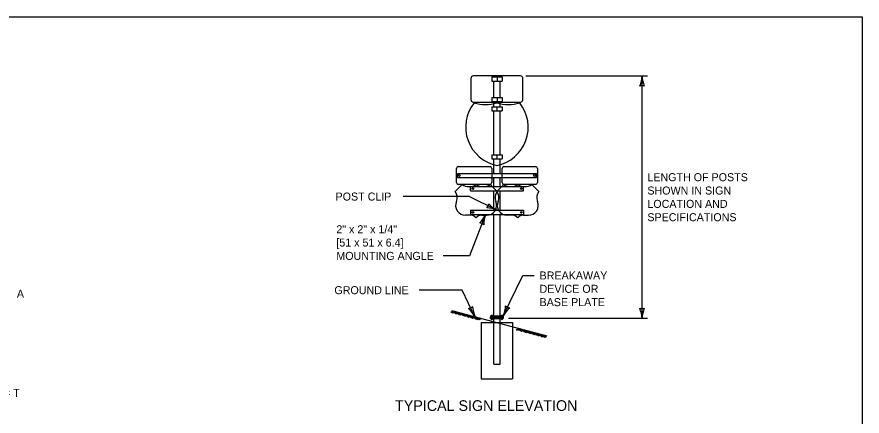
# Model space of a CAD drawing. Extents: x 49991 to 81321, y 49988 to 50028.
# Drawn here: x 50010.41 to 50016.75, y 49996.01 to 49999 of the extents above; entities that cross this region are included whole.
import ezdxf

# ---------------------------------------------------------------- set-up
doc = ezdxf.new("R2010")
doc.units = 0
for name, color, linetype in [('Level 1', 7, 'Continuous'), ('Level 2', 7, 'Continuous'), ('Level 3', 7, 'Continuous'), ('Level 4', 7, 'Continuous')]:
    doc.layers.add(name, color=color, linetype=linetype)

msp = doc.modelspace()

# ---------------------------------------------------------------- linework, layer by layer
at = {"layer": 'Level 1'}
for p, q in [((50013.9732, 49998.5488), (50014.0513, 49998.5488)), ((50013.9732, 49998.5488), (50013.9732, 49998.5175)), ((50014.0122, 49998.5488), (50014.0122, 49998.5175)), ((50014.0513, 49998.5488), (50014.0513, 49998.5175)), ((50013.9732, 49998.5175), (50014.0513, 49998.5175)), ((50013.9888, 49998.3957), (50013.9888, 49998.5175)), ((50014.0357, 49998.3957), (50014.0357, 49998.5175)), ((50013.9732, 49998.3957), (50014.0513, 49998.3957)), ((50013.9732, 49998.3957), (50013.9732, 49998.3644)), ((50013.9732, 49998.3644), (50014.0513, 49998.3644)), ((50013.9881, 49998.3254), (50013.9881, 49998.3644)), ((50014.0122, 49998.3957), (50014.0122, 49998.3644)), ((50014.035, 49998.3254), (50014.035, 49998.3644)), ((50014.0513, 49998.3957), (50014.0513, 49998.3644)), ((50013.9725, 49998.3254), (50014.0506, 49998.3254)), ((50013.9725, 49998.3254), (50013.9725, 49998.2942)), ((50013.9725, 49998.2942), (50014.0506, 49998.2942)), ((50013.9881, 49997.9661), (50013.9881, 49998.2942)), ((50014.0116, 49998.3254), (50014.0116, 49998.2942)), ((50014.035, 49997.9661), (50014.035, 49998.2942)), ((50014.0506, 49998.3254), (50014.0506, 49998.2942)), ((50013.9725, 49997.9661), (50014.0506, 49997.9661)), ((50013.9725, 49997.9661), (50013.9725, 49997.9348)), ((50013.9725, 49997.9348), (50014.0506, 49997.9348)), ((50013.9881, 49997.8254), (50013.9881, 49997.9348)), ((50014.0116, 49997.9661), (50014.0116, 49997.9348)), ((50014.035, 49997.8254), (50014.035, 49997.9348)), ((50014.0506, 49997.9661), (50014.0506, 49997.9348)), ((50013.7149, 49997.8254), (50014.3082, 49997.8254)), ((50013.7149, 49997.7942), (50013.7149, 49997.8254)), ((50013.7149, 49997.7942), (50014.3082, 49997.7942)), ((50013.9881, 49997.7273), (50013.9881, 49997.7942)), ((50014.035, 49997.7273), (50014.035, 49997.7942)), ((50014.3082, 49997.7942), (50014.3082, 49997.8254)), ((50013.814, 49997.7273), (50014.2105, 49997.7273)), ((50013.814, 49997.6961), (50013.814, 49997.7273)), ((50014.2105, 49997.6961), (50014.2105, 49997.7273)), ((50013.814, 49997.6961), (50014.2105, 49997.6961)), ((50013.9881, 49997.5497), (50013.9881, 49997.6961)), ((50014.035, 49997.5497), (50014.035, 49997.6961)), ((50013.814, 49997.5497), (50014.2105, 49997.5497)), ((50013.814, 49997.5497), (50013.814, 49997.5184)), ((50014.2105, 49997.5497), (50014.2105, 49997.5184)), ((50013.814, 49997.5184), (50014.2105, 49997.5184)), ((50013.9881, 49996.3944), (50013.9881, 49997.5184)), ((50014.035, 49996.3944), (50014.035, 49997.5184)), ((50013.666, 49996.7843), (50013.6852, 49996.7954)), ((50013.6712, 49996.7829), (50013.6904, 49996.7939)), ((50013.6718, 49996.7987), (50014.3847, 49996.6075)), ((50013.6766, 49996.7814), (50013.6956, 49996.7925)), ((50013.6862, 49996.7872), (50013.6917, 49996.7774)), ((50013.691, 49996.7899), (50013.6981, 49996.7774)), ((50013.6956, 49996.7925), (50013.7028, 49996.7801)), ((50013.6966, 49996.7759), (50013.7157, 49996.7869)), ((50013.7018, 49996.7744), (50013.721, 49996.7855)), ((50013.7072, 49996.7731), (50013.7262, 49996.7842)), ((50013.7168, 49996.7787), (50013.7224, 49996.7689)), ((50013.7216, 49996.7814), (50013.7287, 49996.7689)), ((50013.7262, 49996.7842), (50013.7335, 49996.7717)), ((50013.7281, 49996.7673), (50013.7474, 49996.7784)), ((50013.7335, 49996.7659), (50013.7525, 49996.7769)), ((50013.7387, 49996.7644), (50013.7578, 49996.7755)), ((50013.7531, 49996.7729), (50013.7604, 49996.7604)), ((50013.7578, 49996.7755), (50013.765, 49996.7631)), ((50013.7485, 49996.7701), (50013.754, 49996.7604)), ((50013.7595, 49996.7594), (50013.7787, 49996.7705)), ((50013.7648, 49996.7581), (50013.784, 49996.7692)), ((50013.7702, 49996.7567), (50013.7892, 49996.7677)), ((50013.7798, 49996.7623), (50013.7854, 49996.7525)), ((50013.7845, 49996.7651), (50013.7917, 49996.7525)), ((50013.7892, 49996.7677), (50013.7965, 49996.7552)), ((50013.7904, 49996.7504), (50013.8095, 49996.7614)), ((50013.7956, 49996.7489), (50013.8147, 49996.7601)), ((50013.801, 49996.7475), (50013.82, 49996.7587)), ((50013.8106, 49996.7532), (50013.8161, 49996.7435)), ((50013.8154, 49996.7561), (50013.8225, 49996.7435)), ((50013.82, 49996.7587), (50013.8272, 49996.7462)), ((50013.8215, 49996.7423), (50013.8406, 49996.7534)), ((50013.8267, 49996.7409), (50013.8457, 49996.7519)), ((50013.832, 49996.7394), (50013.8511, 49996.7505)), ((50013.8417, 49996.7451), (50013.8472, 49996.7354)), ((50013.8465, 49996.7479), (50013.8536, 49996.7354)), ((50013.8511, 49996.7505), (50013.8582, 49996.7381)), ((50013.8518, 49996.7338), (50013.8711, 49996.7449)), ((50013.8572, 49996.7324), (50013.8762, 49996.7435)), ((50013.8625, 49996.7311), (50013.8816, 49996.7422)), ((50013.8722, 49996.7367), (50013.8777, 49996.7269)), ((50013.8768, 49996.7394), (50013.8841, 49996.7269)), ((50013.8816, 49996.7422), (50013.8887, 49996.7297)), ((50013.9645, 49996.7572), (50014.0586, 49996.7572)), ((50013.9645, 49996.7572), (50013.9645, 49996.7487)), ((50013.9645, 49996.7487), (50014.0586, 49996.7487)), ((50013.9645, 49996.7472), (50014.0586, 49996.7472)), ((50013.9645, 49996.7387), (50013.9645, 49996.7472)), ((50013.9645, 49996.7387), (50014.0586, 49996.7387)), ((50013.9786, 49996.7577), (50013.9686, 49996.7577)), ((50013.9686, 49996.7577), (50013.9686, 49996.7572)), ((50013.9783, 49996.7572), (50013.9686, 49996.7572)), ((50013.9686, 49996.7487), (50013.9686, 49996.7472)), ((50013.9686, 49996.7381), (50013.9686, 49996.7387)), ((50013.9686, 49996.7381), (50013.9783, 49996.7381)), ((50013.9693, 49996.7577), (50013.9693, 49996.7609)), ((50013.9693, 49996.7381), (50013.9693, 49996.7349)), ((50013.9703, 49996.7619), (50013.9768, 49996.7619)), ((50013.9703, 49996.7339), (50013.9768, 49996.7339)), ((50013.9703, 49996.7339), (50013.9768, 49996.7339)), ((50013.9708, 49996.7577), (50013.9708, 49996.7572)), ((50013.9708, 49996.7381), (50013.9708, 49996.7387)), ((50013.9714, 49996.7577), (50013.9714, 49996.7609)), ((50013.9714, 49996.7572), (50013.9714, 49996.7387)), ((50013.9714, 49996.7381), (50013.9714, 49996.7349)), ((50013.9717, 49996.7335), (50013.9758, 49996.7339)), ((50013.9717, 49996.7329), (50013.9758, 49996.7332)), ((50013.9717, 49996.7323), (50013.9758, 49996.7326)), ((50013.9717, 49996.7316), (50013.9758, 49996.732)), ((50013.9717, 49996.731), (50013.9758, 49996.7313)), ((50013.9717, 49996.7304), (50013.9758, 49996.7307)), ((50013.9717, 49996.7297), (50013.9758, 49996.7301)), ((50013.9717, 49996.7297), (50013.9755, 49996.7297)), ((50013.9736, 49996.7387), (50013.9736, 49996.7281)), ((50013.9758, 49996.7577), (50013.9758, 49996.7609)), ((50013.9758, 49996.7572), (50013.9758, 49996.7387)), ((50013.9758, 49996.7381), (50013.9758, 49996.7349)), ((50013.9764, 49996.7577), (50013.9764, 49996.7572)), ((50013.9764, 49996.7381), (50013.9764, 49996.7387)), ((50013.9779, 49996.7577), (50013.9779, 49996.7609)), ((50013.9779, 49996.7381), (50013.9779, 49996.7349)), ((50013.9786, 49996.7577), (50013.9786, 49996.7572)), ((50013.9786, 49996.7487), (50013.9786, 49996.7472)), ((50014.0545, 49996.7577), (50014.0445, 49996.7577)), ((50014.0445, 49996.7577), (50014.0445, 49996.7572)), ((50014.0542, 49996.7572), (50014.0445, 49996.7572)), ((50014.0445, 49996.7487), (50014.0445, 49996.7472)), ((50014.0445, 49996.7381), (50014.0445, 49996.7387)), ((50014.0445, 49996.7381), (50014.0542, 49996.7381)), ((50014.0452, 49996.7577), (50014.0452, 49996.7609)), ((50014.0452, 49996.7381), (50014.0452, 49996.7349)), ((50014.0462, 49996.7619), (50014.0527, 49996.7619)), ((50014.0462, 49996.7339), (50014.0527, 49996.7339)), ((50014.0462, 49996.7339), (50014.0527, 49996.7339)), ((50014.0467, 49996.7577), (50014.0467, 49996.7572)), ((50014.0467, 49996.7381), (50014.0467, 49996.7387)), ((50014.0473, 49996.7577), (50014.0473, 49996.7609)), ((50014.0473, 49996.7572), (50014.0473, 49996.7387)), ((50014.0473, 49996.7381), (50014.0473, 49996.7349)), ((50014.0476, 49996.7335), (50014.0517, 49996.7339)), ((50014.0476, 49996.7329), (50014.0517, 49996.7332)), ((50014.0476, 49996.7323), (50014.0517, 49996.7326)), ((50014.0476, 49996.7316), (50014.0517, 49996.732)), ((50014.0476, 49996.731), (50014.0517, 49996.7313)), ((50014.0476, 49996.7304), (50014.0517, 49996.7307)), ((50014.0476, 49996.7297), (50014.0517, 49996.7301)), ((50014.0476, 49996.7297), (50014.0514, 49996.7297)), ((50014.0495, 49996.7387), (50014.0495, 49996.7281)), ((50014.0517, 49996.7577), (50014.0517, 49996.7609)), ((50014.0517, 49996.7572), (50014.0517, 49996.7387)), ((50014.0517, 49996.7381), (50014.0517, 49996.7349)), ((50014.0523, 49996.7577), (50014.0523, 49996.7572)), ((50014.0523, 49996.7381), (50014.0523, 49996.7387)), ((50014.0538, 49996.7577), (50014.0538, 49996.7609)), ((50014.0538, 49996.7381), (50014.0538, 49996.7349)), ((50014.0545, 49996.7577), (50014.0545, 49996.7572)), ((50014.0545, 49996.7487), (50014.0545, 49996.7472)), ((50014.0586, 49996.7572), (50014.0586, 49996.7487)), ((50014.0586, 49996.7472), (50014.0586, 49996.7387)), ((50014.0141, 49996.7069), (50014.1287, 49996.7069)), ((50014.1287, 49996.7069), (50014.1287, 49996.6764)), ((50014.1566, 49996.6539), (50014.1757, 49996.6651)), ((50014.1618, 49996.6525), (50014.181, 49996.6637)), ((50014.1672, 49996.6512), (50014.1862, 49996.6623)), ((50014.1768, 49996.6568), (50014.1824, 49996.6472)), ((50014.1816, 49996.6597), (50014.1887, 49996.6472)), ((50014.1862, 49996.6623), (50014.1935, 49996.6498)), ((50014.1872, 49996.6455), (50014.2065, 49996.6567)), ((50014.1925, 49996.6442), (50014.2116, 49996.6552)), ((50014.1978, 49996.6427), (50014.2168, 49996.6538)), ((50014.2075, 49996.6484), (50014.213, 49996.6387)), ((50014.2122, 49996.6512), (50014.2194, 49996.6387)), ((50014.2168, 49996.6538), (50014.2241, 49996.6413)), ((50014.2187, 49996.6369), (50014.238, 49996.6481)), ((50014.2241, 49996.6355), (50014.2431, 49996.6467)), ((50014.2294, 49996.6342), (50014.2485, 49996.6452)), ((50014.2391, 49996.6398), (50014.2445, 49996.6301)), ((50014.2437, 49996.6425), (50014.251, 49996.6301)), ((50014.2485, 49996.6452), (50014.2556, 49996.6327)), ((50014.2502, 49996.6292), (50014.2694, 49996.6402)), ((50014.2555, 49996.6277), (50014.2745, 49996.6388)), ((50014.2607, 49996.6263), (50014.2798, 49996.6374)), ((50014.2705, 49996.6319), (50014.276, 49996.6223)), ((50014.2752, 49996.6348), (50014.2824, 49996.6223)), ((50014.2798, 49996.6374), (50014.287, 49996.6249)), ((50014.281, 49996.6201), (50014.3002, 49996.6312)), ((50014.2862, 49996.6187), (50014.3054, 49996.6298)), ((50014.2916, 49996.6173), (50014.3106, 49996.6284)), ((50014.3012, 49996.6229), (50014.3067, 49996.6132)), ((50014.306, 49996.6257), (50014.3131, 49996.6132)), ((50014.3106, 49996.6284), (50014.3178, 49996.6159)), ((50014.312, 49996.6119), (50014.3312, 49996.6231)), ((50014.3174, 49996.6105), (50014.3365, 49996.6217)), ((50014.3227, 49996.6092), (50014.3417, 49996.6202)), ((50014.3324, 49996.6148), (50014.3378, 49996.6051)), ((50014.337, 49996.6175), (50014.3442, 49996.6051)), ((50014.3417, 49996.6202), (50014.349, 49996.6077)), ((50014.3425, 49996.6035), (50014.3617, 49996.6147)), ((50014.3478, 49996.6022), (50014.3668, 49996.6132)), ((50014.3531, 49996.6007), (50014.3722, 49996.6118)), ((50014.3628, 49996.6063), (50014.3682, 49996.5967)), ((50014.3675, 49996.6092), (50014.3747, 49996.5967)), ((50014.3722, 49996.6118), (50014.3794, 49996.5993)), ((50013.9881, 49996.3944), (50014.035, 49996.3944))]:
    msp.add_line(p, q, dxfattribs=at)
msp.add_lwpolyline([(49999.3835, 49998.9992), (50016.7501, 49998.9992), (50016.7501, 49987.7988), (49999.3835, 49987.7988)], close=True, dxfattribs=at)
for points in [[(50013.9717, 49996.7297), (50013.9714, 49996.7301), (50013.9717, 49996.7304), (50013.9714, 49996.7307), (50013.9717, 49996.731), (50013.9714, 49996.7313), (50013.9717, 49996.7316), (50013.9714, 49996.732), (50013.9717, 49996.7323), (50013.9714, 49996.7326), (50013.9717, 49996.7329), (50013.9714, 49996.7332), (50013.9717, 49996.7335), (50013.9714, 49996.7339)], [(50013.9758, 49996.7339), (50013.9755, 49996.7335), (50013.9758, 49996.7332), (50013.9755, 49996.7329), (50013.9758, 49996.7326), (50013.9755, 49996.7323), (50013.9758, 49996.732), (50013.9755, 49996.7316), (50013.9758, 49996.7313), (50013.9755, 49996.731), (50013.9758, 49996.7307), (50013.9755, 49996.7304), (50013.9758, 49996.7301), (50013.9755, 49996.7297)], [(50013.9779, 49996.7381), (50013.9786, 49996.7381), (50013.9786, 49996.7381), (50013.9786, 49996.7387)], [(50014.0476, 49996.7297), (50014.0473, 49996.7301), (50014.0476, 49996.7304), (50014.0473, 49996.7307), (50014.0476, 49996.731), (50014.0473, 49996.7313), (50014.0476, 49996.7316), (50014.0473, 49996.732), (50014.0476, 49996.7323), (50014.0473, 49996.7326), (50014.0476, 49996.7329), (50014.0473, 49996.7332), (50014.0476, 49996.7335), (50014.0473, 49996.7339)], [(50014.0517, 49996.7339), (50014.0514, 49996.7335), (50014.0517, 49996.7332), (50014.0514, 49996.7329), (50014.0517, 49996.7326), (50014.0514, 49996.7323), (50014.0517, 49996.732), (50014.0514, 49996.7316), (50014.0517, 49996.7313), (50014.0514, 49996.731), (50014.0517, 49996.7307), (50014.0514, 49996.7304), (50014.0517, 49996.7301), (50014.0514, 49996.7297)], [(50014.0538, 49996.7381), (50014.0545, 49996.7381), (50014.0545, 49996.7381), (50014.0545, 49996.7387)]]:
    msp.add_lwpolyline(points, dxfattribs=at)
for centre in [(50013.7297, 49997.8099), (50014.2934, 49997.8098), (50013.8306, 49997.7121), (50014.1944, 49997.7121), (50013.8306, 49997.5335), (50014.1944, 49997.5335)]:
    msp.add_circle(centre, 0.00663, dxfattribs=at)
for centre, start, end in [((50013.9703, 49996.7609), 0, 180), ((50013.9703, 49996.7349), 180, 0), ((50013.9724, 49996.7609), 90, 180), ((50013.9724, 49996.7349), 180, 270), ((50013.9748, 49996.7609), 0, 90), ((50013.9748, 49996.7349), 270, 0), ((50013.9768, 49996.7609), 0, 180), ((50013.9768, 49996.7349), 180, 0.01245), ((50014.0462, 49996.7609), 0, 180), ((50014.0462, 49996.7349), 180, 0), ((50014.0483, 49996.7609), 90, 180), ((50014.0483, 49996.7349), 180, 270), ((50014.0507, 49996.7609), 0, 90), ((50014.0507, 49996.7349), 270, 0), ((50014.0527, 49996.7609), 0, 180), ((50014.0527, 49996.7349), 180, 0.01245)]:
    msp.add_arc(centre, 0.00105, start, end, dxfattribs=at)
at = {"layer": 'Level 3'}
for p, q in [((50014.2273, 49998.5564), (50015.1397, 49998.5564)), ((50015.0997, 49996.7387), (50015.0997, 49998.5564)), ((50013.96, 49997.8767), (50013.96, 49997.8767)), ((50013.8044, 49997.6522), (50013.3083, 49997.6522)), ((50014.0116, 49997.5497), (50013.8044, 49997.6522)), ((50013.9254, 49997.5184), (50013.8066, 49997.2074)), ((50013.8066, 49997.2074), (50013.6078, 49997.2074)), ((50014.0586, 49996.7572), (50014.2068, 49997.0605)), ((50014.2068, 49997.0605), (50014.2912, 49997.0605)), ((50013.75, 49996.9504), (50013.4278, 49996.9504)), ((50013.8471, 49996.7517), (50013.75, 49996.9504)), ((50015.1397, 49996.7387), (50014.0986, 49996.7387))]:
    msp.add_line(p, q, dxfattribs=at)
for centre, radius, start, end in [((50014.8776, 49998.5656), 0.2223, 337.45601, 357.63952), ((50015.3324, 49998.5679), 0.233, 182.82731, 202.07716), ((50015.0997, 49998.4282), 0.0548, 72.13882, 107.86118), ((50013.8966, 49997.6066), 0.0548, 315.81625, 351.53861), ((50014.1183, 49997.7447), 0.2223, 221.13344, 241.31695), ((50013.9187, 49997.336), 0.233, 66.50474, 85.75459), ((50013.7211, 49997.6062), 0.2223, 316.55071, 336.73422), ((50014.1469, 49997.4461), 0.233, 161.92201, 181.17186), ((50013.8796, 49997.3986), 0.0548, 51.23352, 86.95588), ((50013.7908, 49996.8669), 0.0548, 278.18494, 313.90731), ((50013.6431, 49996.6392), 0.233, 28.87344, 48.12329), ((50014.0507, 49996.841), 0.2223, 183.50214, 203.68564), ((50013.8445, 49996.849), 0.233, 336.78601, 356.03586), ((50014.2542, 49996.6515), 0.2223, 131.41471, 151.59822), ((50014.1149, 49996.8724), 0.0548, 226.09752, 261.81988), ((50015.0997, 49996.8669), 0.0548, 252.13882, 287.86118), ((50014.867, 49996.7272), 0.233, 2.82731, 22.07716), ((50015.3218, 49996.7295), 0.2223, 157.45601, 177.63952)]:
    msp.add_arc(centre, radius, start, end, dxfattribs=at)
at = {"layer": 'Level 4'}
for p, q in [((50014.1873, 49998.5564), (50013.8359, 49998.5564)), ((50013.8163, 49998.5369), (50013.8163, 49998.3806)), ((50014.2068, 49998.3806), (50014.2068, 49998.5369)), ((50013.8359, 49998.3611), (50014.1873, 49998.3611)), ((50013.7078, 49997.7572), (50013.7078, 49997.8634)), ((50013.7211, 49997.8767), (50013.96, 49997.8767)), ((50013.9733, 49997.8634), (50013.9733, 49997.7572)), ((50014.0498, 49997.7572), (50014.0498, 49997.8634)), ((50014.0631, 49997.8767), (50014.302, 49997.8767)), ((50014.3153, 49997.8634), (50014.3153, 49997.7572)), ((50013.7505, 49997.7431), (50013.698, 49997.6908)), ((50013.96, 49997.7439), (50013.7211, 49997.7439)), ((50013.9601, 49997.7431), (50014.0126, 49997.6908)), ((50014.063, 49997.7432), (50014.0105, 49997.6908)), ((50014.302, 49997.7439), (50014.0631, 49997.7439)), ((50014.2726, 49997.7432), (50014.3251, 49997.6908)), ((50013.8134, 49997.5126), (50013.7749, 49997.5126)), ((50013.8972, 49997.5126), (50013.9357, 49997.5126)), ((50014.1259, 49997.5126), (50014.0874, 49997.5126)), ((50014.2097, 49997.5126), (50014.2482, 49997.5126)), ((50013.8944, 49996.7069), (50013.8944, 49996.2851)), ((50013.8944, 49996.7069), (50014.0141, 49996.7069)), ((50014.1287, 49996.6764), (50014.1287, 49996.2851)), ((50013.8944, 49996.2851), (50014.1287, 49996.2851))]:
    msp.add_line(p, q, dxfattribs=at)
for centre, radius, start, end in [((50013.8359, 49998.5369), 0.0195, 90, 180), ((50014.1873, 49998.5369), 0.0195, 0, 90), ((50013.8359, 49998.3806), 0.0195, 180, 270), ((50014.1873, 49998.3806), 0.0195, 270, 360), ((50014.0701, 49998.1728), 0.293, 141.66902, 258.46305), ((50013.9259, 49998.6347), 0.293, 253.00907, 286.99093), ((50013.953, 49998.1728), 0.293, 281.53695, 38.33098), ((50014.0972, 49998.6347), 0.293, 253.00907, 286.99093), ((50013.7211, 49997.8634), 0.0133, 90, 180), ((50013.96, 49997.8634), 0.0133, 0, 90), ((50014.0631, 49997.8634), 0.0133, 90, 180), ((50014.302, 49997.8634), 0.0133, 0, 90), ((50013.7211, 49997.7572), 0.0133, 180, 270), ((50013.8029, 49997.8216), 0.0943, 236.26567, 303.74892), ((50013.9077, 49997.8216), 0.0943, 236.25108, 303.73433), ((50013.96, 49997.7572), 0.0133, 270, 0), ((50014.0631, 49997.7572), 0.0133, 180, 270), ((50014.1154, 49997.8216), 0.0943, 236.26567, 303.74892), ((50014.2202, 49997.8216), 0.0943, 236.25108, 303.73433), ((50014.302, 49997.7572), 0.0133, 270, 0), ((50013.6406, 49997.6451), 0.0734, 336.22855, 38.52813), ((50014.07, 49997.6451), 0.0734, 141.48415, 203.77145), ((50013.9531, 49997.6451), 0.0734, 336.22855, 38.52813), ((50014.3825, 49997.6451), 0.0734, 141.47187, 203.77145), ((50013.7749, 49997.5859), 0.0734, 156.22855, 270), ((50013.9357, 49997.5859), 0.0734, 270, 23.77145), ((50014.0874, 49997.5859), 0.0734, 156.22855, 270), ((50014.2482, 49997.5859), 0.0734, 270, 23.77145), ((50013.8134, 49997.4601), 0.0524, 36.8699, 90), ((50013.8972, 49997.4601), 0.0524, 90, 143.1301), ((50014.1259, 49997.4602), 0.0524, 36.8699, 90), ((50014.2097, 49997.4602), 0.0524, 90, 143.1301)]:
    msp.add_arc(centre, radius, start, end, dxfattribs=at)

# ---------------------------------------------------------------- texts
at = {"layer": 'Level 2'}
for s, height, p in [('LENGTH OF POSTS', 0.06, (50015.1397, 49997.7674)), ('SHOWN IN SIGN', 0.06, (50015.1397, 49997.6674)), ('POST CLIP', 0.06, (50012.8012, 49997.6222)), ('LOCATION AND', 0.06, (50015.1397, 49997.5674)), ('SPECIFICATIONS', 0.06, (50015.1397, 49997.4674)), ('2" x 2" x 1/4"', 0.06, (50012.8072, 49997.3774)), ('[51 x 51 x 6.4]', 0.06, (50012.8072, 49997.2774)), ('MOUNTING ANGLE', 0.06, (50012.8072, 49997.1774)), ('BREAKAWAY', 0.06, (50014.3312, 49997.0305)), ('GROUND LINE', 0.06, (50012.7927, 49996.9204)), ('DEVICE OR', 0.06, (50014.3312, 49996.9305)), ('A', 0.06, (50010.4116, 49996.8938)), ('BASE PLATE', 0.06, (50014.3312, 49996.8305)), ('PLATE THICKNESS = T', 0.06, (50009.5565, 49996.1503)), ('TYPICAL SIGN ELEVATION', 0.08, (50013.2478, 49996.0451))]:
    msp.add_text(s, height=height, dxfattribs=at).set_placement(p)

doc.saveas('drawing.dxf')
